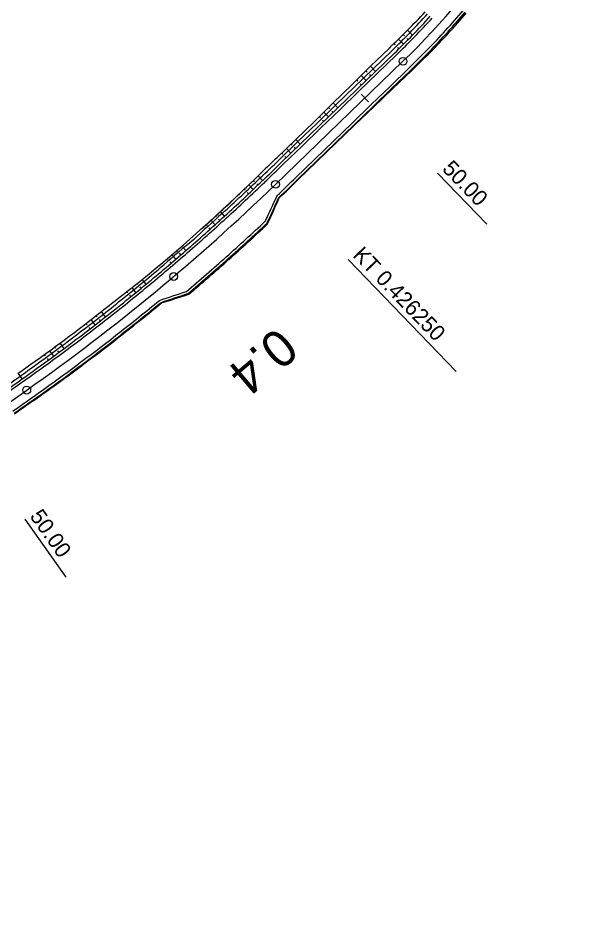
# Model space of a CAD drawing. Extents: x -481656 to -478728, y -1113199 to -1110710.
# Drawn here: x -480321.2 to -480212.6, y -1112822.9 to -1112650.6 of the extents above; entities that cross this region are included whole.
import ezdxf

# ---------------------------------------------------------------- set-up
doc = ezdxf.new("R2010")
doc.units = 0
for name, color, linetype in [('C14_HATCH_SLOPE_L', 7, 'Continuous'), ('C14_HATCH_SLOPE_R', 7, 'Continuous'), ('C14_HECTOMETRY', 7, 'Continuous'), ('C14_HLBODY', 7, 'Continuous'), ('C14_HRANA_TELESO', 7, 'Continuous'), ('C14_KORUNA', 7, 'Continuous'), ('C14_OSA', 7, 'Continuous'), ('C14_PRIKOP', 7, 'Continuous'), ('C14_STANICENI', 7, 'Continuous'), ('C14_VOZOVKA', 7, 'Continuous'), ('C14_ZPEVKRAJ', 7, 'Continuous')]:
    doc.layers.add(name, color=color, linetype=linetype)

msp = doc.modelspace()

# ---------------------------------------------------------------- linework, layer by layer
at = {"layer": 'C14_HATCH_SLOPE_L'}
for p, q in [((-480245.76, -1112653.9), (-480246.73, -1112652.96)), ((-480247.49, -1112655.65), (-480248.45, -1112654.69)), ((-480247.34, -1112654.07), (-480247.58, -1112653.82)), ((-480246.62, -1112654.78), (-480246.86, -1112654.54)), ((-480249.07, -1112655.79), (-480249.32, -1112655.54)), ((-480248.36, -1112656.52), (-480248.6, -1112656.28)), ((-480252.84, -1112660.85), (-480253.79, -1112659.87)), ((-480254.64, -1112662.59), (-480255.57, -1112661.62)), ((-480254.44, -1112660.99), (-480254.68, -1112660.75)), ((-480253.74, -1112661.72), (-480253.97, -1112661.48)), ((-480256.23, -1112662.74), (-480256.46, -1112662.5)), ((-480255.54, -1112663.46), (-480255.77, -1112663.22)), ((-480260.03, -1112667.8), (-480260.92, -1112666.88)), ((-480261.83, -1112669.53), (-480262.7, -1112668.64)), ((-480261.6, -1112667.97), (-480261.81, -1112667.76)), ((-480260.93, -1112668.67), (-480261.16, -1112668.43)), ((-480263.39, -1112669.72), (-480263.59, -1112669.52)), ((-480262.73, -1112670.4), (-480262.96, -1112670.16)), ((-480267.23, -1112674.75), (-480268.07, -1112673.87)), ((-480269.02, -1112676.48), (-480269.87, -1112675.61)), ((-480268.78, -1112674.94), (-480268.97, -1112674.74)), ((-480268.12, -1112675.61), (-480268.36, -1112675.38)), ((-480270.58, -1112676.67), (-480270.77, -1112676.47)), ((-480269.92, -1112677.35), (-480270.15, -1112677.11)), ((-480274.41, -1112681.69), (-480275.26, -1112680.81)), ((-480276.21, -1112683.41), (-480277.05, -1112682.52)), ((-480275.96, -1112681.87), (-480276.15, -1112681.67)), ((-480275.31, -1112682.55), (-480275.54, -1112682.31)), ((-480277.76, -1112683.57), (-480277.94, -1112683.38)), ((-480277.11, -1112684.26), (-480277.35, -1112684.01)), ((-480281.67, -1112688.49), (-480282.44, -1112687.64)), ((-480283.51, -1112690.16), (-480284.28, -1112689.3)), ((-480283.2, -1112688.65), (-480283.36, -1112688.47)), ((-480282.59, -1112689.32), (-480282.82, -1112689.07)), ((-480285.04, -1112690.31), (-480285.2, -1112690.13)), ((-480284.43, -1112690.99), (-480284.66, -1112690.74)), ((-480289.1, -1112695.1), (-480289.69, -1112694.42)), ((-480292.51, -1112696.84), (-480292.62, -1112696.71)), ((-480290.98, -1112696.72), (-480291.64, -1112695.95)), ((-480290.63, -1112695.23), (-480290.67, -1112695.18)), ((-480290.04, -1112695.91), (-480290.31, -1112695.59)), ((-480291.92, -1112697.53), (-480292.16, -1112697.25)), ((-480298.23, -1112701.6), (-480298.39, -1112701.41)), ((-480296.68, -1112701.52), (-480297.42, -1112700.64)), ((-480300.16, -1112703.15), (-480300.34, -1112702.94)), ((-480299.57, -1112703.89), (-480299.78, -1112703.63)), ((-480298.61, -1112703.1), (-480299.36, -1112702.17)), ((-480297.64, -1112702.31), (-480297.86, -1112702.06)), ((-480304.43, -1112707.76), (-480305.21, -1112706.76)), ((-480306.39, -1112709.29), (-480307.17, -1112708.28)), ((-480306.01, -1112707.76), (-480306.19, -1112707.52)), ((-480305.41, -1112708.52), (-480305.61, -1112708.26)), ((-480307.97, -1112709.27), (-480308.16, -1112709.03)), ((-480307.38, -1112710.05), (-480307.58, -1112709.78)), ((-480313.91, -1112713.75), (-480314.1, -1112713.5)), ((-480312.33, -1112713.8), (-480313.1, -1112712.77)), ((-480315.91, -1112715.22), (-480316.09, -1112714.97)), ((-480315.33, -1112716.01), (-480315.53, -1112715.74)), ((-480314.33, -1112715.27), (-480315.09, -1112714.24)), ((-480313.33, -1112714.54), (-480313.53, -1112714.27)), ((-480320.38, -1112719.64), (-480321.15, -1112718.54))]:
    msp.add_line(p, q, dxfattribs=at)
at = {"layer": 'C14_HATCH_SLOPE_R'}
for p, q in [((-480237.37, -1112651.43), (-480237.17, -1112651.61)), ((-480236.33, -1112650.65), (-480236.33, -1112650.65)), ((-480238.21, -1112652.38), (-480238.11, -1112652.47)), ((-480238.02, -1112652.55), (-480238.02, -1112652.55)), ((-480242.53, -1112657.03), (-480242.37, -1112657.18)), ((-480244.31, -1112658.83), (-480244.16, -1112658.98)), ((-480243.42, -1112657.94), (-480243.34, -1112658.01)), ((-480243.26, -1112658.09), (-480243.26, -1112658.09)), ((-480245.21, -1112659.73), (-480245.14, -1112659.8)), ((-480245.07, -1112659.87), (-480245.07, -1112659.87)), ((-480249.72, -1112664.08), (-480249.6, -1112664.2)), ((-480251.51, -1112665.82), (-480251.41, -1112665.93)), ((-480250.61, -1112664.95), (-480250.56, -1112665.01)), ((-480250.51, -1112665.06), (-480250.51, -1112665.06)), ((-480252.41, -1112666.69), (-480252.36, -1112666.74)), ((-480252.32, -1112666.79), (-480252.32, -1112666.79)), ((-480257.8, -1112671.9), (-480257.77, -1112671.94)), ((-480257.74, -1112671.97), (-480257.74, -1112671.97)), ((-480256.91, -1112671.03), (-480256.84, -1112671.11)), ((-480259.6, -1112673.64), (-480259.58, -1112673.67)), ((-480259.55, -1112673.7), (-480259.55, -1112673.7)), ((-480258.7, -1112672.77), (-480258.65, -1112672.83)), ((-480265, -1112678.85), (-480264.97, -1112678.88)), ((-480264.94, -1112678.91), (-480264.94, -1112678.91)), ((-480264.1, -1112677.98), (-480264.04, -1112678.04)), ((-480266.79, -1112680.59), (-480266.77, -1112680.62)), ((-480266.74, -1112680.65), (-480266.74, -1112680.65)), ((-480265.9, -1112679.72), (-480265.84, -1112679.78)), ((-480271.86, -1112686.17), (-480271.82, -1112686.21)), ((-480271.78, -1112686.25), (-480271.78, -1112686.25)), ((-480271.3, -1112684.94), (-480271.23, -1112685.01)), ((-480272.43, -1112687.4), (-480272.33, -1112687.5)), ((-480273, -1112688.62), (-480272.94, -1112688.68)), ((-480272.89, -1112688.74), (-480272.89, -1112688.74)), ((-480277.29, -1112693.28), (-480277.16, -1112693.43)), ((-480279.16, -1112694.98), (-480279.03, -1112695.13)), ((-480278.22, -1112694.14), (-480278.16, -1112694.21)), ((-480278.09, -1112694.28), (-480278.09, -1112694.28)), ((-480280.1, -1112695.83), (-480280.03, -1112695.9)), ((-480279.96, -1112695.98), (-480279.96, -1112695.98)), ((-480284.83, -1112700.01), (-480284.7, -1112700.16)), ((-480286.75, -1112701.66), (-480286.61, -1112701.81)), ((-480285.79, -1112700.83), (-480285.72, -1112700.91)), ((-480285.66, -1112700.99), (-480285.66, -1112700.99)), ((-480287.71, -1112702.48), (-480287.64, -1112702.55)), ((-480287.58, -1112702.63), (-480287.58, -1112702.63)), ((-480293.82, -1112705), (-480293.73, -1112705.11)), ((-480295.76, -1112706.59), (-480295.67, -1112706.7)), ((-480294.79, -1112705.79), (-480294.74, -1112705.85)), ((-480294.7, -1112705.91), (-480294.7, -1112705.91)), ((-480296.74, -1112707.38), (-480296.69, -1112707.44)), ((-480296.65, -1112707.49), (-480296.65, -1112707.49)), ((-480302.64, -1112712.07), (-480302.6, -1112712.13)), ((-480302.56, -1112712.19), (-480302.56, -1112712.19)), ((-480301.65, -1112711.3), (-480301.57, -1112711.41)), ((-480304.63, -1112713.61), (-480304.59, -1112713.67)), ((-480304.55, -1112713.73), (-480304.55, -1112713.73)), ((-480303.64, -1112712.84), (-480303.55, -1112712.96)), ((-480309.64, -1112717.41), (-480309.56, -1112717.52)), ((-480311.66, -1112718.9), (-480311.58, -1112719.01)), ((-480310.65, -1112718.16), (-480310.61, -1112718.21)), ((-480310.57, -1112718.27), (-480310.57, -1112718.27)), ((-480312.68, -1112719.64), (-480312.64, -1112719.7)), ((-480312.6, -1112719.75), (-480312.6, -1112719.75)), ((-480318.81, -1112724.03), (-480318.77, -1112724.08)), ((-480318.74, -1112724.12), (-480318.74, -1112724.12)), ((-480317.78, -1112723.31), (-480317.72, -1112723.41)), ((-480320.85, -1112725.47), (-480320.82, -1112725.52)), ((-480320.79, -1112725.56), (-480320.79, -1112725.56)), ((-480319.83, -1112724.75), (-480319.77, -1112724.84))]:
    msp.add_line(p, q, dxfattribs=at)
at = {"layer": 'C14_HECTOMETRY'}
msp.add_circle((-480291.42, -1112700.05), 0.75, dxfattribs=at)
at = {"layer": 'C14_HLBODY'}
msp.add_line((-480258.06, -1112696.83), (-480237.42, -1112718.19), dxfattribs=at)
for centre in [(-480247.6, -1112658.91), (-480271.95, -1112682.44), (-480319.49, -1112721.76)]:
    msp.add_circle(centre, 0.75, dxfattribs=at)
at = {"layer": 'C14_HRANA_TELESO'}
for p, q in [((-480253.79, -1112659.87), (-480250.2, -1112656.39)), ((-480257.35, -1112663.38), (-480253.79, -1112659.87)), ((-480249.6, -1112664.2), (-480245.98, -1112660.75)), ((-480260.92, -1112666.88), (-480257.35, -1112663.38)), ((-480253.22, -1112667.65), (-480249.6, -1112664.2)), ((-480264.48, -1112670.39), (-480260.92, -1112666.88)), ((-480256.84, -1112671.11), (-480253.22, -1112667.65)), ((-480268.07, -1112673.87), (-480264.48, -1112670.39)), ((-480260.46, -1112674.56), (-480256.84, -1112671.11)), ((-480271.67, -1112677.34), (-480268.07, -1112673.87)), ((-480264.04, -1112678.04), (-480260.46, -1112674.56)), ((-480267.63, -1112681.52), (-480264.04, -1112678.04))]:
    msp.add_line(p, q, dxfattribs=at)
for centre, radius, start, end in [((-480350.22, -1112549.35), 146.44, 314.9702, 316.8803), ((-480351.48, -1112550.64), 152.51, 317.5927, 319.5026), ((-480557.16, -1112342.27), 439.2, 314.3397, 314.9766), ((-480351.2, -1112550.38), 152.49, 315.5394, 317.4493), ((-480565.27, -1112333.2), 457.42, 314.2679, 314.9042), ((-480135.72, -1112821.65), 198.26, 133.2911, 134.7329), ((-480550.75, -1112395.6), 396.54, 313.2913, 314.0075), ((-480515.45, -1112434.89), 343.74, 309.3665, 313.9112), ((-480409.51, -1112538.89), 201.17, 313.4213, 314.8475), ((-480553.45, -1112398.11), 396.57, 313.1073, 313.8236), ((-480640.54, -1112522.73), 403.39, 335.5045, 336.2793), ((-480549.72, -1112394.62), 396.6, 311.653, 312.3692), ((-480550.61, -1112395.44), 404.44, 312.5414, 313.2576), ((-480550.6, -1112395.42), 404.45, 311.8223, 312.5385), ((-480549.89, -1112394.78), 404.45, 310.97, 311.6862), ((-480549.71, -1112394.63), 404.45, 310.2209, 310.9371), ((-480544.32, -1112390.32), 396.55, 307.7915, 308.5078), ((-480548.09, -1112393.36), 396.49, 307.7753, 308.4915), ((-480414.01, -1112320.03), 403.42, 287.347, 288.1204), ((-480549.79, -1112394.7), 402.39, 308.8031, 309.5193), ((-480549.07, -1112394.15), 396.47, 307.2409, 307.9571), ((-480549.81, -1112394.71), 402.39, 308.0906, 308.8068), ((-480549.67, -1112394.62), 396.47, 306.6344, 307.3506), ((-480549.82, -1112394.73), 402.39, 307.3777, 308.0939), ((-480549.59, -1112394.56), 396.46, 305.9036, 306.6198), ((-480546.99, -1112392.72), 396.44, 304.7268, 305.443), ((-480549.8, -1112394.71), 402.39, 306.658, 307.3742), ((-480549.34, -1112394.38), 402.38, 305.8607, 306.5769), ((-480548.93, -1112394.1), 402.37, 305.0737, 305.7899), ((-481012.18, -1111736.08), 1207.1, 304.88445, 305.12192)]:
    msp.add_arc(centre, radius, start, end, dxfattribs=at)
at = {"layer": 'C14_KORUNA'}
for p, q in [((-480252.84, -1112660.85), (-480249.25, -1112657.38)), ((-480249.72, -1112664.08), (-480246.12, -1112660.61)), ((-480256.44, -1112664.32), (-480252.84, -1112660.85)), ((-480253.31, -1112667.56), (-480249.72, -1112664.08)), ((-480260.03, -1112667.8), (-480256.44, -1112664.32)), ((-480256.91, -1112671.03), (-480253.31, -1112667.56)), ((-480263.63, -1112671.27), (-480260.03, -1112667.8)), ((-480267.23, -1112674.75), (-480263.63, -1112671.27)), ((-480260.5, -1112674.51), (-480256.91, -1112671.03)), ((-480270.82, -1112678.22), (-480267.23, -1112674.75)), ((-480264.1, -1112677.98), (-480260.5, -1112674.51)), ((-480267.69, -1112681.46), (-480264.1, -1112677.98))]:
    msp.add_line(p, q, dxfattribs=at)
for centre, radius, start, end in [((-480351.83, -1112551.04), 147.75, 315.882, 317.7918), ((-480351.83, -1112551.04), 152.25, 317.7918, 319.7017), ((-480351.83, -1112551.04), 152.25, 315.882, 317.7918), ((-480560.52, -1112341.82), 443.25, 314.6088, 315.2456), ((-480566.88, -1112335.45), 456.75, 314.6097, 315.2461), ((-480410.74, -1112536.89), 198.88, 313.275, 314.7136), ((-480549.9, -1112394.79), 397.75, 313.1214, 313.8376), ((-480409.18, -1112538.52), 201.12, 313.2809, 314.7073), ((-480549.9, -1112394.79), 397.75, 312.4052, 313.1214), ((-480638.26, -1112517.75), 403.25, 334.736, 335.5065), ((-480549.9, -1112394.79), 397.75, 311.689, 312.4052), ((-480549.9, -1112394.79), 404.25, 312.4052, 313.1214), ((-480549.9, -1112394.79), 397.75, 310.9728, 311.689), ((-480549.9, -1112394.79), 404.25, 311.689, 312.4052), ((-480549.9, -1112394.79), 397.75, 310.2566, 310.9728), ((-480549.9, -1112394.79), 404.25, 310.9728, 311.689), ((-480549.9, -1112394.79), 397.75, 309.5404, 310.2566), ((-480549.9, -1112394.79), 404.25, 310.2566, 310.9728), ((-480549.9, -1112394.79), 397.75, 308.8242, 309.5404), ((-480417.57, -1112321.2), 403.25, 287.8715, 288.6421), ((-480549.9, -1112394.79), 397.75, 308.108, 308.8242), ((-480549.9, -1112394.79), 402.25, 308.8242, 309.5404), ((-480549.9, -1112394.79), 397.75, 307.3918, 308.108), ((-480549.9, -1112394.79), 402.25, 308.108, 308.8242), ((-480549.9, -1112394.79), 397.75, 306.6756, 307.3918), ((-480549.9, -1112394.79), 402.25, 307.3918, 308.108), ((-480549.9, -1112394.79), 397.75, 305.9594, 306.6756), ((-480549.9, -1112394.79), 402.25, 306.6756, 307.3918), ((-480549.9, -1112394.79), 397.75, 305.2432, 305.9594), ((-480549.9, -1112394.79), 402.25, 305.9594, 306.6756), ((-481009.83, -1111745.73), 1193.25, 305.0557, 305.29565), ((-480549.9, -1112394.79), 402.25, 305.2432, 305.9594), ((-481015.02, -1111738.37), 1206.75, 305.05694, 305.29448)]:
    msp.add_arc(centre, radius, start, end, dxfattribs=at)
at = {"layer": 'C14_OSA'}
for p, q in [((-480271.95, -1112682.45), (-480247.6, -1112658.91)), ((-480462.96, -1112822.86), (-480319.49, -1112721.76))]:
    msp.add_line(p, q, dxfattribs=at)
for centre, radius, start, end in [((-480351.83, -1112551.04), 150, 314.0166, 338.1186), ((-480549.9, -1112394.79), 400, 305.1722, 314.0166)]:
    msp.add_arc(centre, radius, start, end, dxfattribs=at)
at = {"layer": 'C14_PRIKOP'}
for p, q in [((-480253.3, -1112660.37), (-480249.71, -1112656.9)), ((-480256.9, -1112663.84), (-480253.3, -1112660.37)), ((-480260.5, -1112667.32), (-480256.9, -1112663.84)), ((-480264.09, -1112670.79), (-480260.5, -1112667.32)), ((-480267.69, -1112674.27), (-480264.09, -1112670.79)), ((-480271.28, -1112677.74), (-480267.69, -1112674.27))]:
    msp.add_line(p, q, dxfattribs=at)
for centre, radius, start, end in [((-480351.83, -1112551.04), 147.08, 315.882, 317.7918), ((-480559.58, -1112342.76), 441.25, 314.6087, 315.2456), ((-480410.97, -1112536.65), 198.54, 313.2742, 314.7145), ((-480549.3, -1112394.22), 397.08, 313.0022, 313.7184), ((-480549.9, -1112394.79), 397.07, 312.4052, 313.1214), ((-480180.38, -1112804.11), 154.39, 131.2251, 133.9765), ((-480201.02, -1112801.72), 138.97, 128.5303, 131.6146), ((-480550.53, -1112395.32), 397.08, 309.6596, 310.3758), ((-480549.9, -1112394.79), 397.08, 308.8242, 309.5404), ((-480549.9, -1112394.79), 397.08, 308.108, 308.8242), ((-480549.9, -1112394.79), 397.08, 307.3918, 308.108), ((-480549.9, -1112394.79), 397.08, 306.6756, 307.3918), ((-480549.9, -1112394.79), 397.08, 305.9594, 306.6756), ((-480549.9, -1112394.79), 397.08, 305.2432, 305.9594), ((-481009.07, -1111746.82), 1191.25, 305.05551, 305.29583)]:
    msp.add_arc(centre, radius, start, end, dxfattribs=at)
at = {"layer": 'C14_STANICENI'}
for p, q in [((-480254.18, -1112666.66), (-480255.57, -1112665.22)), ((-480240.98, -1112680.32), (-480231.6, -1112690.03)), ((-480319.82, -1112746.46), (-480312.04, -1112757.5))]:
    msp.add_line(p, q, dxfattribs=at)
at = {"layer": 'C14_VOZOVKA'}
for p, q in [((-480252.49, -1112661.21), (-480248.9, -1112657.73)), ((-480250.06, -1112663.73), (-480246.47, -1112660.25)), ((-480256.09, -1112664.68), (-480252.49, -1112661.21)), ((-480253.66, -1112667.2), (-480250.06, -1112663.73)), ((-480259.69, -1112668.16), (-480256.09, -1112664.68)), ((-480257.25, -1112670.67), (-480253.66, -1112667.2)), ((-480263.28, -1112671.63), (-480259.69, -1112668.16)), ((-480260.85, -1112674.15), (-480257.25, -1112670.67)), ((-480266.88, -1112675.11), (-480263.28, -1112671.63)), ((-480264.45, -1112677.62), (-480260.85, -1112674.15)), ((-480270.47, -1112678.58), (-480266.88, -1112675.11)), ((-480268.04, -1112681.1), (-480264.45, -1112677.62))]:
    msp.add_line(p, q, dxfattribs=at)
for centre, radius, start, end in [((-480351.83, -1112551.04), 151.75, 317.7918, 319.7017), ((-480351.83, -1112551.04), 148.25, 315.882, 317.7918), ((-480351.83, -1112551.04), 151.75, 315.882, 317.7918), ((-480561.23, -1112341.11), 444.75, 314.6089, 315.2457), ((-480566.18, -1112336.15), 455.25, 314.6096, 315.246), ((-480410.57, -1112537.07), 199.12, 313.2757, 314.7129), ((-480409.36, -1112538.34), 200.88, 313.2803, 314.708), ((-480549.9, -1112394.79), 398.25, 313.1214, 313.8376), ((-480638.22, -1112517.75), 402.75, 334.7603, 335.531), ((-480549.9, -1112394.79), 398.25, 312.4052, 313.1214), ((-480549.9, -1112394.79), 398.25, 311.689, 312.4052), ((-480549.9, -1112394.79), 403.75, 312.4052, 313.1214), ((-480549.9, -1112394.79), 398.25, 310.9728, 311.689), ((-480549.9, -1112394.79), 403.75, 311.689, 312.4052), ((-480549.9, -1112394.79), 398.25, 310.2566, 310.9728), ((-480549.9, -1112394.79), 403.75, 310.9728, 311.689), ((-480549.9, -1112394.79), 398.25, 309.5404, 310.2566), ((-480549.9, -1112394.79), 403.75, 310.2566, 310.9728), ((-480549.9, -1112394.79), 398.25, 308.8242, 309.5404), ((-480417.57, -1112321.24), 402.75, 287.8471, 288.6177), ((-480549.9, -1112394.79), 398.25, 308.108, 308.8242), ((-480549.9, -1112394.79), 401.75, 308.8242, 309.5404), ((-480549.9, -1112394.79), 398.25, 307.3918, 308.108), ((-480549.9, -1112394.79), 401.75, 308.108, 308.8242), ((-480549.9, -1112394.79), 398.25, 306.6756, 307.3918), ((-480549.9, -1112394.79), 401.75, 307.3918, 308.108), ((-480549.9, -1112394.79), 401.75, 306.6756, 307.3918), ((-480549.9, -1112394.79), 398.25, 305.9594, 306.6756), ((-480549.9, -1112394.79), 398.25, 305.2432, 305.9594), ((-480549.9, -1112394.79), 401.75, 305.9594, 306.6756), ((-481010.41, -1111744.91), 1194.75, 305.05584, 305.29552), ((-480549.9, -1112394.79), 401.75, 305.2432, 305.9594), ((-481014.44, -1111739.19), 1205.25, 305.05681, 305.29461)]:
    msp.add_arc(centre, radius, start, end, dxfattribs=at)
at = {"layer": 'C14_ZPEVKRAJ'}
for p, q in [((-480252.49, -1112661.21), (-480248.9, -1112657.73)), ((-480250.06, -1112663.73), (-480246.47, -1112660.25)), ((-480256.09, -1112664.68), (-480252.49, -1112661.21)), ((-480253.66, -1112667.2), (-480250.06, -1112663.73)), ((-480259.69, -1112668.16), (-480256.09, -1112664.68)), ((-480257.25, -1112670.67), (-480253.66, -1112667.2)), ((-480263.28, -1112671.63), (-480259.69, -1112668.16)), ((-480260.85, -1112674.15), (-480257.25, -1112670.67)), ((-480266.88, -1112675.11), (-480263.28, -1112671.63)), ((-480264.45, -1112677.62), (-480260.85, -1112674.15)), ((-480270.47, -1112678.58), (-480266.88, -1112675.11)), ((-480268.04, -1112681.1), (-480264.45, -1112677.62))]:
    msp.add_line(p, q, dxfattribs=at)
for centre, radius, start, end in [((-480351.83, -1112551.04), 151.75, 317.7918, 319.7017), ((-480351.83, -1112551.04), 148.25, 315.882, 317.7918), ((-480351.83, -1112551.04), 151.75, 315.882, 317.7918), ((-480561.23, -1112341.11), 444.75, 314.6089, 315.2457), ((-480566.18, -1112336.15), 455.25, 314.6096, 315.246), ((-480410.57, -1112537.07), 199.12, 313.2757, 314.7129), ((-480409.36, -1112538.34), 200.88, 313.2803, 314.708), ((-480549.9, -1112394.79), 398.25, 313.1214, 313.8376), ((-480638.22, -1112517.75), 402.75, 334.7603, 335.531), ((-480549.9, -1112394.79), 398.25, 312.4052, 313.1214), ((-480549.9, -1112394.79), 398.25, 311.689, 312.4052), ((-480549.9, -1112394.79), 403.75, 312.4052, 313.1214), ((-480549.9, -1112394.79), 398.25, 310.9728, 311.689), ((-480549.9, -1112394.79), 403.75, 311.689, 312.4052), ((-480549.9, -1112394.79), 398.25, 310.2566, 310.9728), ((-480549.9, -1112394.79), 403.75, 310.9728, 311.689), ((-480549.9, -1112394.79), 398.25, 309.5404, 310.2566), ((-480549.9, -1112394.79), 403.75, 310.2566, 310.9728), ((-480549.9, -1112394.79), 398.25, 308.8242, 309.5404), ((-480417.57, -1112321.24), 402.75, 287.8471, 288.6177), ((-480549.9, -1112394.79), 398.25, 308.108, 308.8242), ((-480549.9, -1112394.79), 401.75, 308.8242, 309.5404), ((-480549.9, -1112394.79), 398.25, 307.3918, 308.108), ((-480549.9, -1112394.79), 401.75, 308.108, 308.8242), ((-480549.9, -1112394.79), 398.25, 306.6756, 307.3918), ((-480549.9, -1112394.79), 401.75, 307.3918, 308.108), ((-480549.9, -1112394.79), 401.75, 306.6756, 307.3918), ((-480549.9, -1112394.79), 398.25, 305.9594, 306.6756), ((-480549.9, -1112394.79), 398.25, 305.2432, 305.9594), ((-480549.9, -1112394.79), 401.75, 305.9594, 306.6756), ((-481010.41, -1111744.91), 1194.75, 305.05584, 305.29552), ((-480549.9, -1112394.79), 401.75, 305.2432, 305.9594), ((-481014.44, -1111739.19), 1205.25, 305.05681, 305.29461)]:
    msp.add_arc(centre, radius, start, end, dxfattribs=at)

# ---------------------------------------------------------------- texts
at = {"layer": 'C14_HECTOMETRY'}
msp.add_text('0.4', height=7, rotation=220.211, dxfattribs=at).set_placement((-480271.59, -1112709.48))
at = {"layer": 'C14_HLBODY'}
msp.add_text('KT 0.426250', height=3, rotation=314.0166, dxfattribs=at).set_placement((-480257.34, -1112696.13))
at = {"layer": 'C14_STANICENI'}
for height, rotation, p in [(3, 314.0166, (-480240.26, -1112679.63)), (2.999, 305.1722, (-480319.01, -1112745.89))]:
    msp.add_text('50.00', height=height, rotation=rotation, dxfattribs=at).set_placement(p)

doc.saveas('drawing.dxf')
